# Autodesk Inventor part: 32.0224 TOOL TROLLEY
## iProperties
Created: 2011-07
Part Number: 32.0224 TOOL TROLLEY
Document SubType Name: Modeling
Designer: Administrator
Density: 7.85 g/cm^3
Material: Steel
Mass: 245.334 g
Surface Area: 161.886 cm^2
Volume: 31.2527 cm^3
Author: Administrator
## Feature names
1. Base1
